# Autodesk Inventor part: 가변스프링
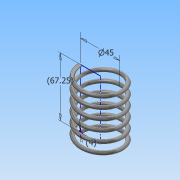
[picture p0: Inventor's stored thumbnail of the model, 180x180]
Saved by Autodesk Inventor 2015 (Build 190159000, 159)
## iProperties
Created: 2016-02
Part Number: 가변스프링
Material: 스테인레스 스틸
Document SubType Name: Modeling
Designer: Administrator
Density: 8 g/cm^3
Appearance: 반연마
Mass: 84.1995 g
Surface Area: 106.448 cm^2
Volume: 10.5249 cm^3
Author: Administrator
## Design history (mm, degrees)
sketch "스케치1"
  geometry: L1 (0, 0)-(22.5, 0); L2 (22.5, 0)-(22.5, 67.25); L3 (22.5, 67.25)-(0, 67.25); L4 (0, 67.25)-(0, 0); C1 r 2 at (22.5, 0)
  constraints: 8 end point, 2 parallel, 1 centre point, 1 coincident, 1 horizontal, 1 perpendicular
  dimensions: "d0" = 45 diameter of L2 L4; "d1" = 67.25 distance between parallel lines of L3 L1 (derived); "d2" = 4 diameter of C1 (derived)
feature "코일1" sketch "스케치1" pitch "d3" = 10; turns "d5" = 6; dims "d4" = 67.25 (= d1), "d6" = 0, angle "d7" = 90 deg, angle "d8" = 90 deg, "d9" = 0, "d10" = 0
sketch "스케치2"
  geometry: L1 (-20.5, 0)-(-24.5, 0) reference; 1 further point
  constraints: 1 horizontal alignment
extrude "돌출1" cut sketch "스케치2" stored distance "d11" = 10; taper "d12" = 0 deg
node "작업 평면1"
sketch "스케치3"
  geometry: L1 (-2, 0)-(2, 0) reference; 1 further point
  constraints: 1 horizontal alignment
extrude "돌출2" cut sketch "스케치3" stored distance "d13" = 10; taper "d14" = 0 deg
node "솔리드1"
node "절단 모서리 투영1"
node "절단 모서리 투영2"
